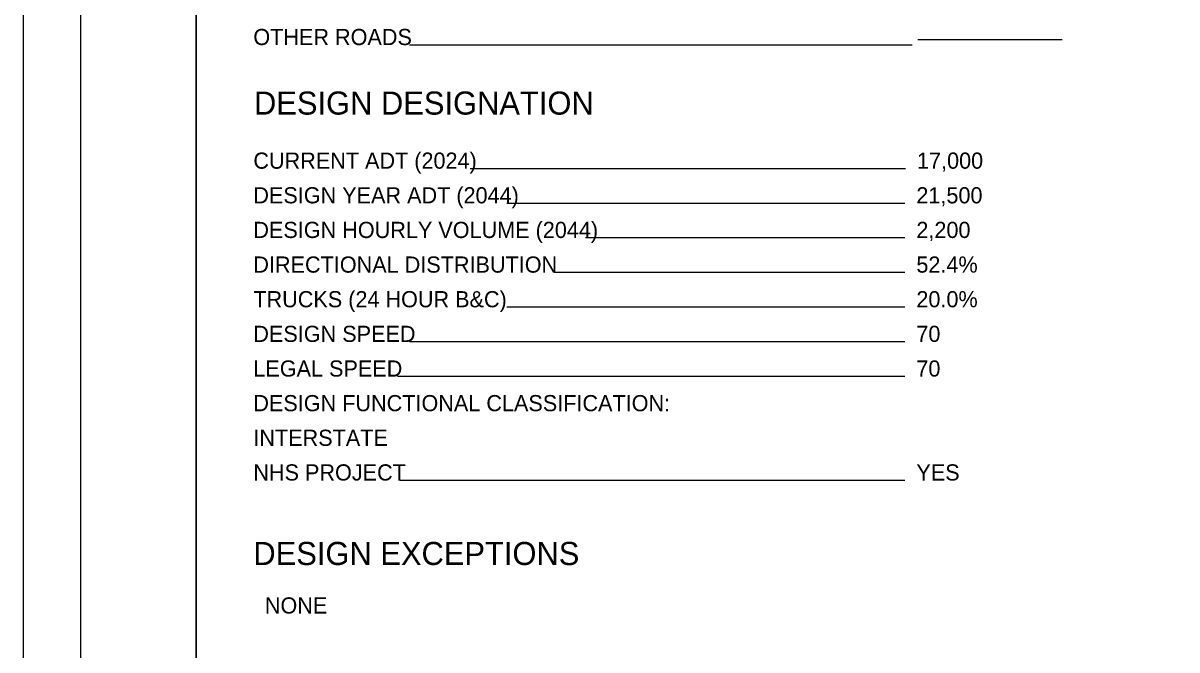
# Model space of a CAD drawing. Extents: x 0 to 34, y 0 to 22.
# Drawn here: x 0 to 9.99, y 5.64 to 11.07 of the extents above; entities that cross this region are included whole.
import ezdxf

# ---------------------------------------------------------------- set-up
doc = ezdxf.new("R2010")
doc.units = 0
for name, color, linetype in [('SH_Border', 7, 'Continuous'), ('SH_Cut_Line', 7, 'Continuous'), ('SH_Data', 7, 'Continuous'), ('SH_Text', 7, 'Continuous')]:
    doc.layers.add(name, color=color, linetype=linetype)

msp = doc.modelspace()

# ---------------------------------------------------------------- linework, layer by layer
at = {"layer": 'SH_Border'}
for points in [[(0.5, 21.5), (1.5, 21.5), (1.5, 0.5), (0.5, 0.5)], [(1.5, 21.5), (33.5, 21.5), (33.5, 0.5), (1.5, 0.5)]]:
    msp.add_lwpolyline(points, close=True, dxfattribs=at)
at = {"layer": 'SH_Cut_Line'}
msp.add_lwpolyline([(0, 0), (34, 0), (34, 22), (0, 22)], close=True, dxfattribs=at)
at = {"layer": 'SH_Data'}
for p, q in [((9, 10.9223), (7.75, 10.9223)), ((7.7, 10.8767), (3.3471, 10.8767)), ((7.6424, 9.8062), (3.871, 9.8062)), ((7.6368, 9.5062), (4.1885, 9.5062)), ((7.6368, 9.2062), (4.8723, 9.2062)), ((7.6368, 8.9062), (4.6037, 8.9062)), ((7.6368, 8.6062), (4.1885, 8.6062)), ((7.6368, 8.3062), (3.346, 8.3062)), ((7.6368, 8.0062), (3.2422, 8.0062)), ((7.6368, 7.1062), (3.2669, 7.1062))]:
    msp.add_line(p, q, dxfattribs=at)

# ---------------------------------------------------------------- texts
msp.add_text('DESIGN DESIGNATION', height=0.2, dxfattribs=at).set_placement((2, 10.2747))
at = {"layer": 'SH_Text'}
for s, height, p in [('OTHER ROADS', 0.14, (1.9944, 10.8767)), ('CURRENT ADT (2024)', 0.14, (1.9944, 9.8062)), ('17,000', 0.14, (7.7424, 9.8062)), ('DESIGN YEAR ADT (2044)', 0.14, (1.9944, 9.5062)), ('21,500', 0.14, (7.7368, 9.5062)), ('DESIGN HOURLY VOLUME (2044)', 0.14, (1.9944, 9.2062)), ('2,200', 0.14, (7.7368, 9.2062)), ('DIRECTIONAL DISTRIBUTION', 0.14, (1.9944, 8.9062)), ('52.4%', 0.14, (7.7368, 8.9062)), ('TRUCKS (24 HOUR B&C)', 0.14, (1.9944, 8.6062)), ('20.0%', 0.14, (7.7368, 8.6062)), ('DESIGN SPEED', 0.14, (1.9944, 8.3062)), ('70', 0.14, (7.7368, 8.3062)), ('LEGAL SPEED', 0.14, (1.9944, 8.0062)), ('70', 0.14, (7.7368, 8.0062)), ('DESIGN FUNCTIONAL CLASSIFICATION:', 0.14, (1.9944, 7.7062)), ('INTERSTATE', 0.14, (1.9944, 7.4062)), ('NHS PROJECT', 0.14, (1.9944, 7.1062)), ('YES', 0.14, (7.7368, 7.1062)), ('DESIGN EXCEPTIONS', 0.2, (1.9944, 6.3744)), ('NONE                                   ', 0.14, (2.0941, 5.9544))]:
    msp.add_text(s, height=height, dxfattribs=at).set_placement(p)

doc.saveas('drawing.dxf')
